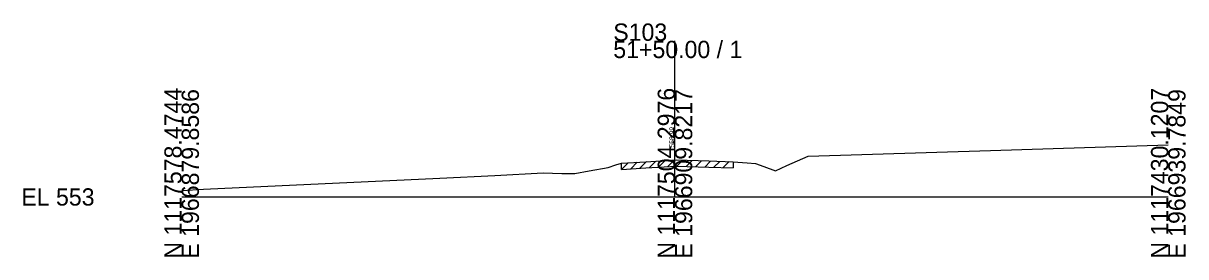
# Model space of a CAD drawing. Extents: x -26 to 163, y -10 to 45020.
# Drawn here: x -25.7 to 162.8, y 11490.3 to 11528.2 of the extents above; entities that cross this region are included whole.
import ezdxf

# ---------------------------------------------------------------- set-up
doc = ezdxf.new("R2010")
doc.units = 0
for name, color, linetype in [('RD_GPK_XS_Cell', 7, 'Continuous'), ('RD_XS_ExGround', 7, 'Continuous'), ('RD_XS_ExPaveRet', 7, 'Continuous'), ('RD_XS_TX_Elev_EX', 7, 'Continuous')]:
    doc.layers.add(name, color=color, linetype=linetype)

msp = doc.modelspace()

# ---------------------------------------------------------------- linework, layer by layer
at = {"layer": 'RD_GPK_XS_Cell'}
for p, q in [((80, 11500), (80, 11525.31)), ((0, 11500), (80, 11500)), ((80, 11500), (160, 11500))]:
    msp.add_line(p, q, dxfattribs=at)
at = {"layer": 'RD_XS_ExGround'}
for p, q in [((131.18, 11507.54), (160, 11508.44)), ((98.16, 11505.08), (101.61, 11506.62)), ((101.61, 11506.62), (131.18, 11507.54)), ((66.1, 11504.21), (69.16, 11504.76)), ((69.16, 11504.76), (70.41, 11505.21)), ((70.41, 11505.21), (71.33, 11505.47)), ((71.33, 11505.47), (75.26, 11505.71)), ((75.26, 11505.71), (80.27, 11506)), ((80.27, 11506), (85.47, 11505.83)), ((85.47, 11505.83), (89.42, 11505.7)), ((89.42, 11505.7), (91.69, 11505.53)), ((91.69, 11505.53), (93.04, 11505.43)), ((93.04, 11505.43), (94.39, 11504.95)), ((94.39, 11504.95), (96.33, 11504.24)), ((96.33, 11504.24), (98.16, 11505.08)), ((3.54, 11501.28), (41.89, 11503.03)), ((41.89, 11503.03), (50.81, 11503.45)), ((50.81, 11503.45), (58.64, 11503.89)), ((58.64, 11503.89), (61.68, 11503.82)), ((61.68, 11503.82), (63.78, 11503.8)), ((63.78, 11503.8), (66.1, 11504.21)), ((0, 11501.05), (3.54, 11501.28))]:
    msp.add_line(p, q, dxfattribs=at)
at = {"layer": 'RD_XS_ExPaveRet'}
for p, q in [((71.33, 11504.47), (72.39, 11505.53)), ((71.33, 11504.47), (71.33, 11505.47)), ((71.33, 11504.47), (75.26, 11504.71)), ((72.83, 11504.56), (73.89, 11505.63)), ((74.33, 11504.65), (75.39, 11505.72)), ((75.26, 11504.71), (80.27, 11505)), ((75.83, 11504.74), (76.89, 11505.81)), ((77.33, 11504.83), (78.39, 11505.89)), ((78.83, 11504.92), (79.89, 11505.98)), ((80.27, 11505), (85.47, 11504.83)), ((80.33, 11505), (81.29, 11505.97)), ((81.83, 11504.95), (82.79, 11505.92)), ((83.33, 11504.9), (84.29, 11505.87)), ((84.83, 11504.85), (85.79, 11505.82)), ((85.47, 11504.83), (89.42, 11504.7)), ((86.33, 11504.8), (87.3, 11505.77)), ((87.83, 11504.75), (88.8, 11505.72)), ((89.42, 11505.7), (89.42, 11504.7))]:
    msp.add_line(p, q, dxfattribs=at)

# ---------------------------------------------------------------- texts
at = {"layer": 'RD_GPK_XS_Cell'}
for s, p in [('S103', (70, 11525.31)), ('51+50.00 / 1', (70, 11522.51)), ('EL 553', (-26, 11498.6))]:
    msp.add_text(s, height=2.8, dxfattribs=at).set_placement(p)
for s, p in [('N 1117578.4744', (0, 11490)), ('N 1117504.2976', (80, 11490)), ('N 1117430.1207', (160, 11490)), ('E 1966879.8586', (2.8, 11490)), ('E 1966909.8217', (82.8, 11490)), ('E 1966939.7849', (162.8, 11490))]:
    msp.add_text(s, height=2.8, rotation=90, dxfattribs=at).set_placement(p)
at = {"layer": 'RD_XS_TX_Elev_EX'}
msp.add_text('558.99', height=0.8, rotation=90, dxfattribs=at).set_placement((79.9, 11507.99))

doc.saveas('drawing.dxf')
